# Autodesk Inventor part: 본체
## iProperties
Created: 2015-06
Part Number: 본체
Material: 알루미늄-6061
Document SubType Name: Modeling
Designer: elite
Mass: 3321.71 g
Surface Area: 2317.29 cm^2
Volume: 1225.72 cm^3
Density: 2.71 g/cm^3
Author: elite
